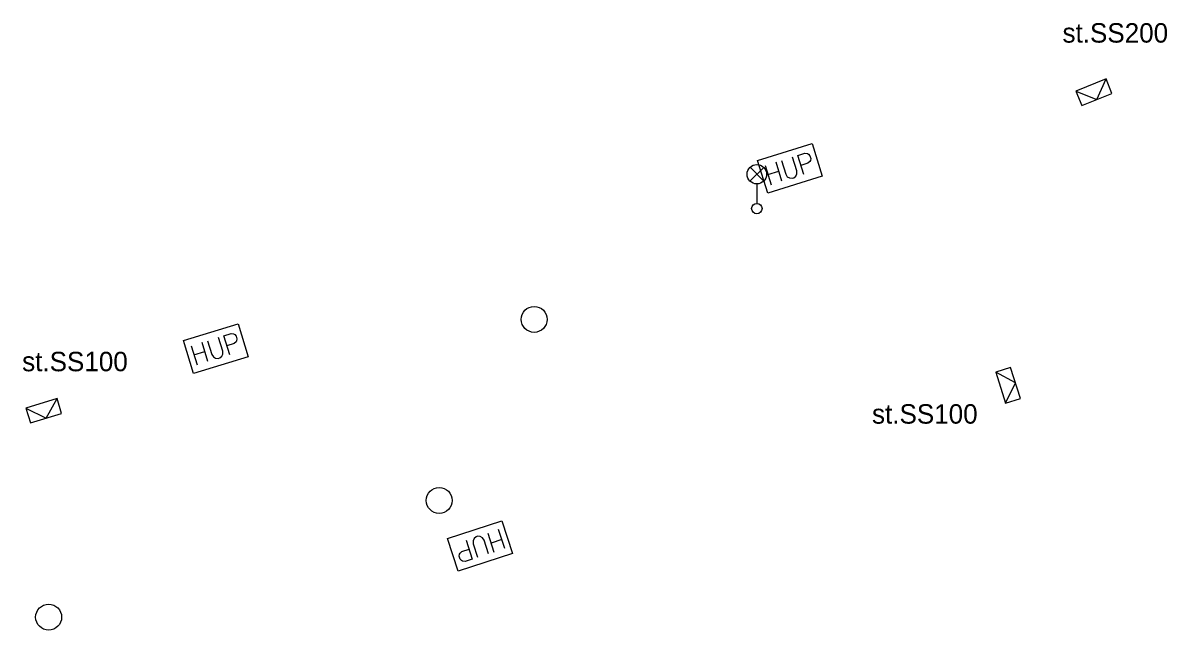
# Model space of a CAD drawing. Extents: x -762500 to -761250, y -1152983 to -1152297.
# Drawn here: x -761738.61 to -761694.52, y -1152507.54 to -1152484.13 of the extents above; entities that cross this region are included whole.
import ezdxf

# ---------------------------------------------------------------- set-up
doc = ezdxf.new("R2010")
doc.units = 0
for name, color, linetype in [('Vrstva 1', 7, 'Continuous'), ('Vrstva 2', 7, 'Continuous'), ('Vrstva 9', 7, 'Continuous')]:
    doc.layers.add(name, color=color, linetype=linetype)

msp = doc.modelspace()

# ---------------------------------------------------------------- linework, layer by layer
at = {"layer": 'Vrstva 1'}
for points in [[(-761697.81, -1152487.313), (-761696.65, -1152486.847), (-761696.873, -1152486.291), (-761698.033, -1152486.756)], [(-761700.17, -1152498.605), (-761700.55, -1152497.415), (-761701.122, -1152497.597), (-761700.742, -1152498.788)], [(-761738.318, -1152499.552), (-761737.122, -1152499.188), (-761737.297, -1152498.614), (-761738.493, -1152498.979)]]:
    msp.add_lwpolyline(points, close=True, dxfattribs=at)
for points in [[(-761698.033, -1152486.756), (-761697.23, -1152487.08), (-761696.873, -1152486.291)], [(-761700.742, -1152498.788), (-761700.36, -1152498.01), (-761701.122, -1152497.597)], [(-761738.493, -1152498.979), (-761737.72, -1152499.37), (-761737.297, -1152498.614)]]:
    msp.add_lwpolyline(points, dxfattribs=at)
at = {"layer": 'Vrstva 9'}
for p, q in [((-761710.594, -1152490.228), (-761710.066, -1152489.7)), ((-761710.058, -1152490.225), (-761710.586, -1152489.696)), ((-761710.33, -1152490.34), (-761710.33, -1152491.09))]:
    msp.add_line(p, q, dxfattribs=at)
for points in [[(-761710.302, -1152489.436), (-761708.201, -1152488.783), (-761707.809, -1152490.044), (-761709.911, -1152490.696), (-761710.302, -1152489.436)], [(-761709.36, -1152490.237), (-761709.588, -1152489.502)], [(-761709.38, -1152489.437), (-761709.216, -1152489.964), (-761709.155, -1152490.058), (-761709.068, -1152490.108), (-761708.968, -1152490.116), (-761708.908, -1152490.097), (-761708.83, -1152490.034), (-761708.792, -1152489.946), (-761708.794, -1152489.833), (-761708.958, -1152489.306)], [(-761708.75, -1152489.242), (-761708.477, -1152489.157), (-761708.378, -1152489.165), (-761708.335, -1152489.189), (-761708.285, -1152489.249), (-761708.252, -1152489.354), (-761708.26, -1152489.433), (-761708.281, -1152489.476), (-761708.358, -1152489.539), (-761708.631, -1152489.624)], [(-761708.521, -1152489.977), (-761708.75, -1152489.242)], [(-761710.01, -1152489.633), (-761709.782, -1152490.368)], [(-761709.903, -1152489.98), (-761709.481, -1152489.849)], [(-761732.417, -1152496.379), (-761730.313, -1152495.736), (-761729.928, -1152496.999), (-761732.032, -1152497.641), (-761732.417, -1152496.379)], [(-761730.864, -1152496.192), (-761730.591, -1152496.109), (-761730.492, -1152496.117), (-761730.45, -1152496.142), (-761730.399, -1152496.202), (-761730.367, -1152496.307), (-761730.375, -1152496.386), (-761730.397, -1152496.429), (-761730.474, -1152496.491), (-761730.747, -1152496.575)], [(-761730.639, -1152496.929), (-761730.864, -1152496.192)], [(-761732.127, -1152496.577), (-761731.902, -1152497.314)], [(-761731.479, -1152497.185), (-761731.704, -1152496.448)], [(-761731.495, -1152496.385), (-761731.334, -1152496.913), (-761731.273, -1152497.007), (-761731.187, -1152497.057), (-761731.087, -1152497.065), (-761731.027, -1152497.047), (-761730.949, -1152496.984), (-761730.91, -1152496.896), (-761730.912, -1152496.784), (-761731.073, -1152496.256)], [(-761732.021, -1152496.925), (-761731.598, -1152496.796)], [(-761719.746, -1152504.586), (-761721.838, -1152505.265), (-761722.246, -1152504.01), (-761720.154, -1152503.33), (-761719.746, -1152504.586)], [(-761720.04, -1152504.392), (-761720.278, -1152503.66)], [(-761721.534, -1152504.067), (-761721.296, -1152504.8)], [(-761720.668, -1152504.596), (-761720.838, -1152504.071), (-761720.901, -1152503.978), (-761720.989, -1152503.929), (-761721.088, -1152503.923), (-761721.148, -1152503.942), (-761721.225, -1152504.006), (-761721.263, -1152504.095), (-761721.259, -1152504.207), (-761721.088, -1152504.732)], [(-761720.698, -1152503.796), (-761720.461, -1152504.529)], [(-761720.152, -1152504.047), (-761720.573, -1152504.183)], [(-761721.296, -1152504.8), (-761721.568, -1152504.888), (-761721.667, -1152504.881), (-761721.709, -1152504.857), (-761721.761, -1152504.798), (-761721.795, -1152504.694), (-761721.788, -1152504.615), (-761721.767, -1152504.571), (-761721.691, -1152504.508), (-761721.419, -1152504.419)]]:
    msp.add_lwpolyline(points, dxfattribs=at)
for centre, radius in [((-761710.33, -1152489.965), 0.375), ((-761710.33, -1152491.29), 0.2), ((-761718.91, -1152495.56), 0.5), ((-761722.57, -1152502.54), 0.5), ((-761737.62, -1152507.04), 0.5)]:
    msp.add_circle(centre, radius, dxfattribs=at)

# ---------------------------------------------------------------- texts
at = {"layer": 'Vrstva 2'}
for s, p in [('st.SS200', (-761698.55, -1152484.89)), ('st.SS100', (-761738.64, -1152497.56)), ('st.SS100', (-761705.89, -1152499.58))]:
    msp.add_text(s, height=0.75, dxfattribs=at).set_placement(p)

doc.saveas('drawing.dxf')
